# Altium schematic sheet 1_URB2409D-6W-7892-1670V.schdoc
size 289 x 200 mm; Name: default297x210; Symbol: default297x210; Device: default297x210; Date: 2025.06.10; Rev: V1.1; Size: "A4"; Id: /; File: URB2409D-6W-7892-1670V; Sheet: /; @Page No: 1; @Page Count: 1; @Schematic Name: URB2409D-6W-7892-1670V; @Project Name: URB2409D-6W-7892-1670V; @Board Name: URB2409D-6W-7892-1670V; @Update Date: 2025-06-10; @Create Time: 15:27:42; @Update Time: 09:38:51; @Page Name: URB2409D-6W-7892-1670V; @Create Date: 2025-06-09
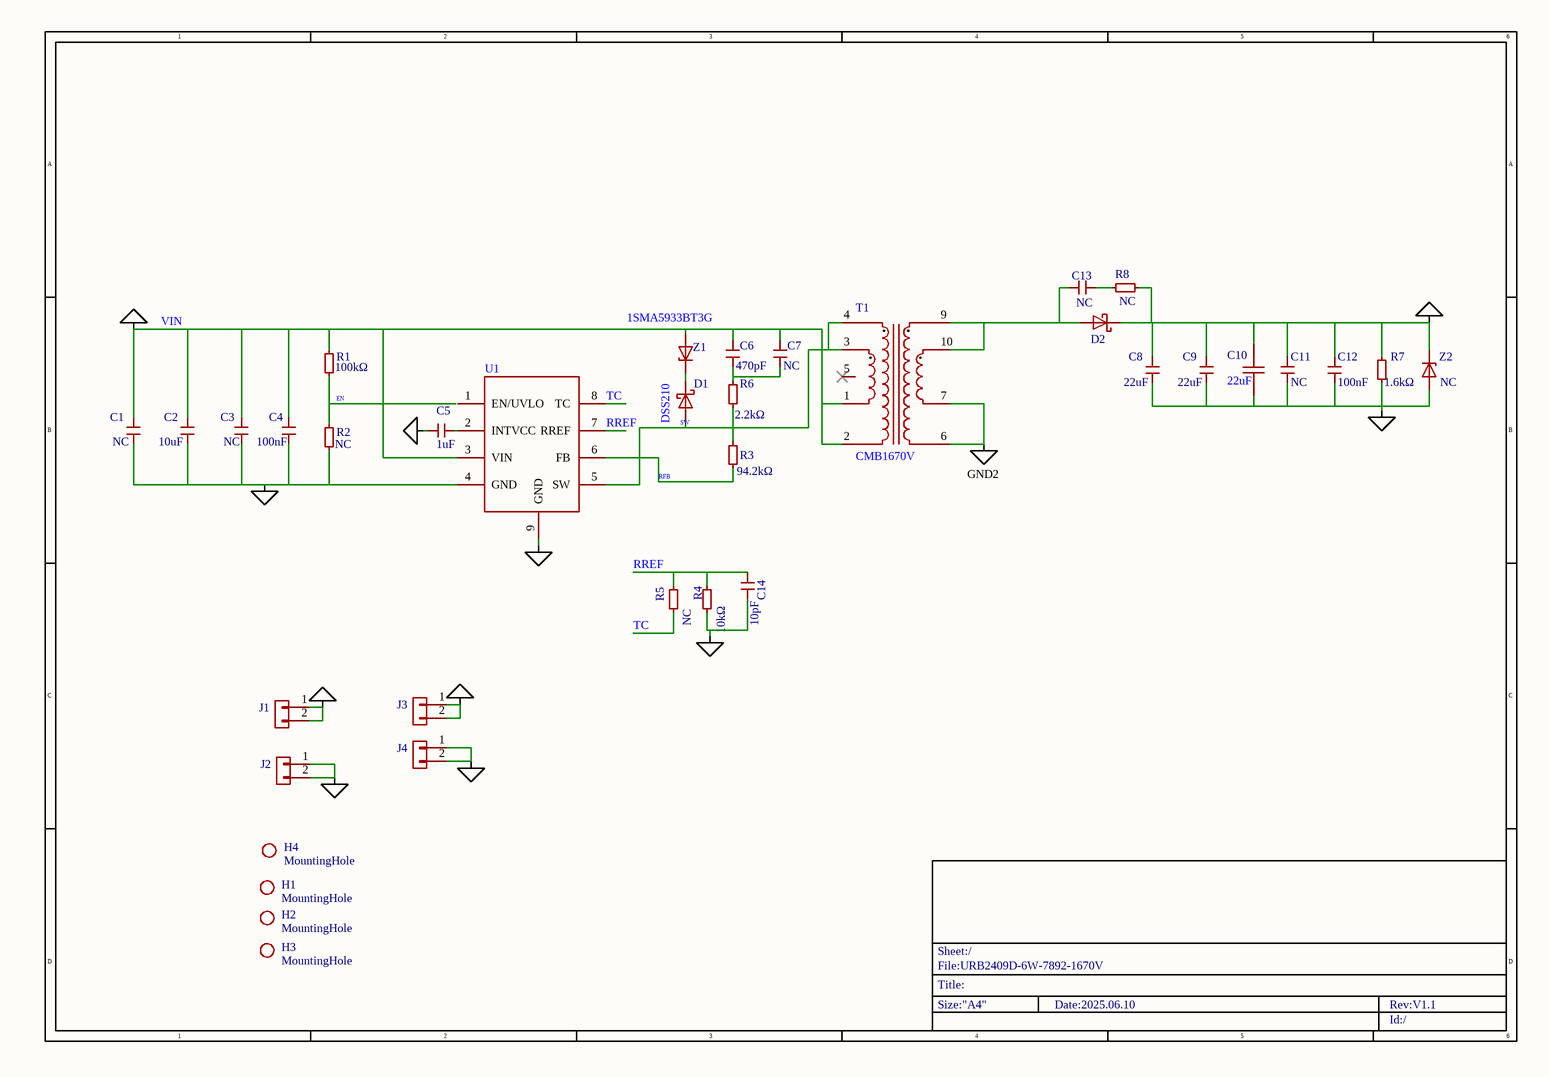
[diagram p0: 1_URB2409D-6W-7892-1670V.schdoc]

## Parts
C1  NC  [C1206]
C2  10uF  [C1206]
C3  NC  [C0805]
C4  100nF  [C0603]
C5  1uF  [C0603]
C6  470pF  [C0603]
C7  NC  [C0603]
C8  22uF  [C1206]
C9  22uF  [C1206]
C10  22uF  [C1206]
C11  NC  [C0603]
C12  100nF  [C0603]
C13  NC  [C0603]
C14  10pF  [C0603]
D1  DSS210  [SOD-123_L2.8-W1.8-LS3.7-FD]
D2  SSL510B  [SMB_L4.6-W3.5-LS5.3-RD]  (value not drawn)
H1  value MountingHole  [MountingHole:MountingHole_3.2mm_M3_DIN965]  (hidden comment: Mechanical_MountingHole)
H2  value MountingHole  [MountingHole:MountingHole_3.2mm_M3_DIN965]  (hidden comment: Mechanical_MountingHole)
H3  value MountingHole  [MountingHole:MountingHole_3.2mm_M3_DIN965]  (hidden comment: Mechanical_MountingHole)
H4  value MountingHole  [MountingHole:MountingHole_3.2mm_M3_DIN965]  (hidden comment: Mechanical_MountingHole)
J1  Connector_Generic_Conn_01x02  [Connector_PinHeader_2.54mm:PinHeader_1x02_P2.54mm_Vertical]  (value not drawn)
J2  Connector_Generic_Conn_01x02  [Connector_PinHeader_2.54mm:PinHeader_1x02_P2.54mm_Vertical]  (value not drawn)
J3  Connector_Generic_Conn_01x02  [Connector_PinHeader_2.54mm:PinHeader_1x02_P2.54mm_Vertical]  (value not drawn)
J4  Connector_Generic_Conn_01x02  [Connector_PinHeader_2.54mm:PinHeader_1x02_P2.54mm_Vertical]  (value not drawn)
R1  100kΩ  [R0603]
R2  NC  [R0603]
R3  94.2kΩ  [R0603]
R4  10kΩ  [R0603]
R5  value NC  [R0603]  (hidden comment: Device_R_Small)
R6  2.2kΩ  [R0603]
R7  1.6kΩ  [R0603]
R8  value NC  [R0603]  (hidden comment: Device_R_Small)
T1  CMB1670V  [XFMR-SMD_CMB1670V]
U1  (no value)  [ESOP-8_L4.9-W3.9-P1.27-LS6.0-TL-EP3.3]
Z1  1SMA5933BT3G  [SMA_L4.3-W2.6-LS5.2-RD]
Z2  value NC  [DIODE-SMA]  (hidden comment: Diode_BZV55C75)

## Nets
GND1: C1.2 C2.2 C3.2 C4.1 C5.1 C14.1 J2.1(Pin_1) J2.2(Pin_2) R2.2 R4.2 U1.4(GND) U1.9(GND)
GND2: C8.2 C9.2 C10.1 C11.1 C12.1 J4.1(Pin_1) J4.2(Pin_2) R7.1 T1.6 T1.7 Z2.2(A)
VIN: C1.1 C2.1 C3.1 C4.2 C6.1 C7.1 J1.1(Pin_1) J1.2(Pin_2) R1.1 T1.1 T1.2 U1.3(VIN) Z1.2(A)
VOUT: C8.1 C9.1 C10.2 C11.2 C12.2 D2.1(K) J3.1(Pin_1) J3.2(Pin_2) R7.2 R8.1 Z2.1(K)
EN: R1.2 R2.1
RFB: R3.1 U1.6(FB)
RREF: C14.2 R4.1 R5.2 U1.7(RREF)
SW: D1.2(A) R3.2 R6.1 T1.3 T1.4 U1.5(SW)
TC: R5.1 U1.8(TC)
NetC5_2: C5.2 U1.2(INTVCC)
NetC6_2: C6.2 C7.2 R6.2
NetC13_1: C13.1 R8.2
NetC13_2: C13.2 D2.2(A) T1.9 T1.10
NetD1_1: D1.1(K) Z1.1(K)

Not connected (* = marked no-connect by the designer): T1 5*; U1 1(EN/UVLO)

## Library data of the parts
C1 = CC1206KKX5R9BB106: Manufacturer: YAGEO(国巨); Symbol: MY_C; Add into BOM: no; Convert to PCB: yes; Tolerance: ±10%; Voltage Rated: 50V; Temperature Coefficient: X5R
C2 = CC1206KKX7R8BB106: Manufacturer: YAGEO(国巨); Symbol: MY_C; Add into BOM: yes; Tolerance: ±10%; Voltage Rated: 25V; Temperature Coefficient: X7R
C3 = CGA0805X5R476M100MT: Manufacturer: HRE(芯声); Symbol: MY_C; Add into BOM: no; Convert to PCB: yes; Tolerance: ±20%; Voltage Rating: 10V; Temperature Coefficient: X5R
C4 C12 = CC0603KRX7R9BB104: Manufacturer: YAGEO(国巨); Symbol: MY_C; Add into BOM: yes; Tolerance: ±10%; Voltage Rated: 50V; Temperature Coefficient: X7R
C5 = CC0603KRX7R9BB105: Manufacturer: YAGEO(国巨); Symbol: MY_C; Add into BOM: yes; Tolerance: ±10%; Voltage Rated: 50V; Temperature Coefficient: X7R
C6 = CC0603KRX7R9BB471: Manufacturer: YAGEO(国巨); Symbol: My_library_C; Add into BOM: yes; Tolerance: ±10%; Voltage Rated: 50V; Temperature Coefficient: X7R
C7 = CC0603KRX7R9BB471: Manufacturer: YAGEO(国巨); Symbol: My_library_C; Add into BOM: no; Convert to PCB: yes; Tolerance: ±10%; Voltage Rated: 50V; Temperature Coefficient: X7R
C8 C9 = 1206X226M250NT: Manufacturer: FH(风华); Symbol: MY_C; Add into BOM: yes; Tolerance: ±20%; Voltage Rating: 25V; Temperature Coefficient: X5R
C10 = 1206X226M250NT: Manufacturer: FH(风华); Add into BOM: yes; Tolerance: ±20%; Voltage Rating: 25V; Temperature Coefficient: X5R
C11 = CC0603KRX7R9BB104: Manufacturer: YAGEO(国巨); Symbol: MY_C; Add into BOM: no; Convert to PCB: yes; Tolerance: ±10%; Voltage Rated: 50V; Temperature Coefficient: X7R
C13 = CGA0603X7R104K500JT: Manufacturer: HRE(芯声); Symbol: My_library_C; Add into BOM: no; Convert to PCB: yes; Value: 100nF; Tolerance: ±10%; Voltage Rating: 50V; Temperature Coefficient: X7R
C14 = CC0603JRNPO9BN100: Manufacturer: YAGEO(国巨); Symbol: My_library_C; Add into BOM: yes; Tolerance: ±5%; Voltage Rated: 50V; Temperature Coefficient: NP0
D1 = DSS210: Manufacturer: CJ(江苏长电/长晶); Symbol: My library_DSS210; Add into BOM: yes; Diode Configuration: 独立式; Forward Voltage (Vf@If): 850mV@2A; Reverse Voltage (Vr): 100V; Rectified Current: 2A; Reverse Leakage Current (Ir): 100uA@100V
D2 = SSL510B_C41410776: Manufacturer: 宏嘉诚; Symbol: My library_DSS210; Add into BOM: yes; Diode Configuration: 独立式; Voltage - Forward(Vf@If): 600mV@5.0A; Voltage - DC Reverse(Vr): 100V; Current - Rectified: 5A; Reverse Leakage Current (Ir): 1mA@100V
H1-H4 = Mechanical_MountingHole: Users: REF**; ki_fp_filters: MountingHole*; Add into BOM: yes
J1-J4 = Connector_Generic_Conn_01x02: Users: REF**; ki_fp_filters: Connector*:*_1x??_*; Add into BOM: yes
R1 = RC0603FR-07100KL: Manufacturer: YAGEO(国巨); Symbol: Device_R_Small; Add into BOM: yes; Tolerance: ±1%; Power(Watts): 100mW; Overload Voltage (Max): 75V; Temperature Coefficient: ±100ppm/℃
R2 = RC0603FR-0710KL: Manufacturer: YAGEO(国巨); Symbol: Device_R_Small; Add into BOM: no; Convert to PCB: yes; Tolerance: ±1%; Power(Watts): 100mW; Overload Voltage (Max): 75V; Temperature Coefficient: ±100ppm/℃
R3 = RT0603BRD0794K2L: Manufacturer: YAGEO(国巨); Symbol: Device_R_Small; Add into BOM: yes; Tolerance: ±0.1%; Power(Watts): 100mW; Temperature Coefficient: ±25ppm/℃
R4 = RC0603FR-0710KL: Manufacturer: YAGEO(国巨); Symbol: Device_R_Small; Add into BOM: yes; Tolerance: ±1%; Power(Watts): 100mW; Overload Voltage (Max): 75V; Temperature Coefficient: ±100ppm/℃
R5 R8 = Device_R_Small: Users: REF**; ki_fp_filters: R_*; Add into BOM: no; Convert to PCB: yes; Origin Footprint: MYLibrary:R0603
R6 = RC0603FR-072K2L: Manufacturer: YAGEO(国巨); Symbol: Device_R_Small; Add into BOM: yes; Tolerance: ±1%; Power(Watts): 100mW; Voltage-Supply(Max): 75V; Temperature Coefficient: ±100ppm/℃
R7 = RC0603FR-071K6L: Manufacturer: YAGEO(国巨); Symbol: Device_R_Small; Add into BOM: yes; Tolerance: ±1%; Power(Watts): 100mW; Overload Voltage (Max): 75V; Temperature Coefficient: ±100ppm/℃
T1 = CMB1670V: Manufacturer: coileasy(线易); Add into BOM: yes
U1 = CMP7892: Add into BOM: yes
Z1 = 1SMA5933BT3G: Manufacturer: onsemi(安森美); Symbol: Diode_BZV55C75; Add into BOM: yes; Diode Configuration: 独立式; Zener Voltage (Nom): 22V; Reverse Leakage Current (Ir): 500nA@16.7V; Zener Voltage (Range): 20.9V~23.1V; Power Dissipation: 1.5W; Zener Impedance (Zzt): 17.5Ω
Z2 = Diode_BZV55C75: Users: REF**; ki_fp_filters: D*MiniMELF*; Add into BOM: yes; Origin Footprint: Diode_SMD:D_SMA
